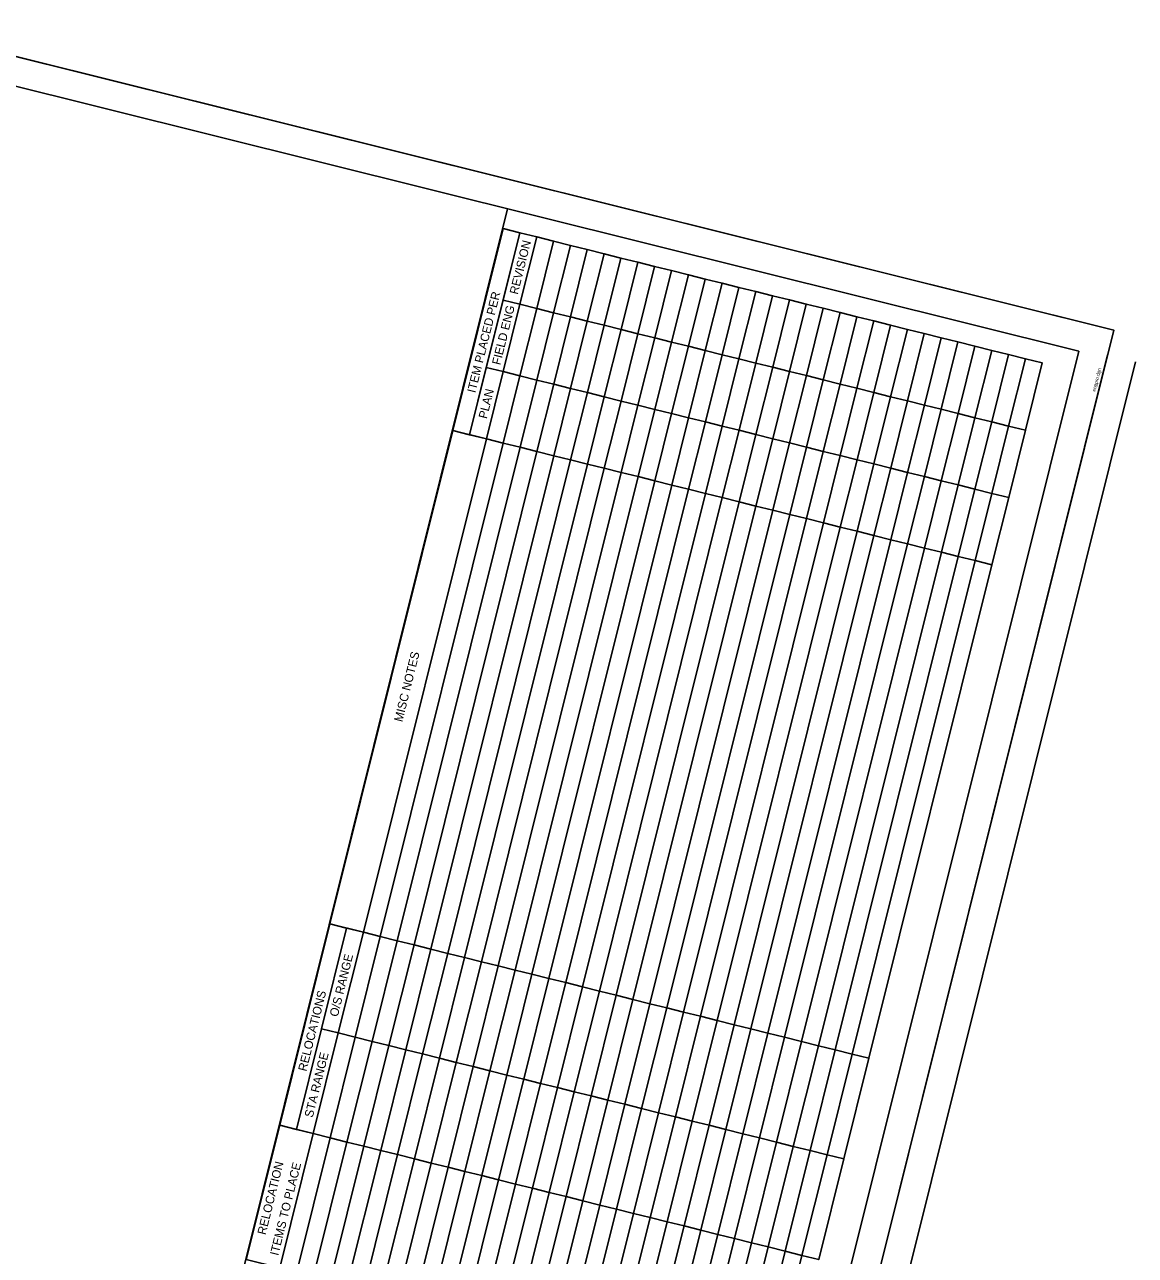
# Model space of a CAD drawing. Extents: x 2304552 to 2306093, y 413849 to 415858.
# Drawn here: x 2305126 to 2306093, y 414787 to 415858 of the extents above; entities that cross this region are included whole.
import ezdxf

# ---------------------------------------------------------------- set-up
doc = ezdxf.new("R2010")
doc.units = 0
for name, color, linetype in [('RD_SHT_Bndy', 7, 'Continuous'), ('RD_SHT_Iplotshp', 7, 'Continuous'), ('RD_SHT_MjGrid', 7, 'Continuous'), ('RD_SHT_Snap', 7, 'Continuous'), ('RD_SHT_TX', 7, 'Continuous')]:
    doc.layers.add(name, color=color, linetype=linetype)

msp = doc.modelspace()

# ---------------------------------------------------------------- linework, layer by layer
at = {"layer": 'RD_SHT_Bndy'}
for p, q in [((2306043.7, 415574), (2305024.9, 415827.9)), ((2305141.5, 414072.6), (2305546.4, 415697.9)), ((2305638.8, 413948.7), (2306043.7, 415574)), ((2306068.6, 415570.6), (2305643.1, 413862.8)), ((2306092.9, 415564.5), (2305667.4, 413856.7))]:
    msp.add_line(p, q, dxfattribs=at)
at = {"layer": 'RD_SHT_Iplotshp'}
msp.add_lwpolyline([(2304572.5, 414115.5), (2305006.6, 415858.2), (2306074, 415592.3), (2305639.9, 413849.6)], close=True, dxfattribs=at)
at = {"layer": 'RD_SHT_MjGrid'}
for points in [[(2305498.7, 415504.8), (2305542.5, 415680.6), (2305557.1, 415676.9), (2305513.4, 415501.2)], [(2305557.2, 415614.7), (2305571.8, 415673.3), (2305557.1, 415676.9), (2305542.5, 415618.3)], [(2305571.8, 415673.3), (2305557.2, 415614.7), (2305571.8, 415611), (2305586.4, 415669.6)], [(2305586.4, 415669.6), (2305571.8, 415611), (2305586.5, 415607.4), (2305601.1, 415666)], [(2305601.1, 415666), (2305586.5, 415607.4), (2305601.2, 415603.7), (2305615.8, 415662.3)], [(2305615.8, 415662.3), (2305601.2, 415603.7), (2305615.8, 415600.1), (2305630.4, 415658.7)], [(2305630.4, 415658.7), (2305615.8, 415600.1), (2305630.5, 415596.4), (2305645.1, 415655)], [(2305645.1, 415655), (2305630.5, 415596.4), (2305645.2, 415592.8), (2305659.8, 415651.4)], [(2305659.8, 415651.4), (2305645.2, 415592.8), (2305659.8, 415589.1), (2305674.4, 415647.7)], [(2305674.4, 415647.7), (2305659.8, 415589.1), (2305674.5, 415585.5), (2305689.1, 415644)], [(2305689.1, 415644), (2305674.5, 415585.5), (2305689.2, 415581.8), (2305703.8, 415640.4)], [(2305703.8, 415640.4), (2305689.2, 415581.8), (2305703.8, 415578.2), (2305718.4, 415636.7)], [(2305718.4, 415636.7), (2305703.8, 415578.2), (2305718.5, 415574.5), (2305733.1, 415633.1)], [(2305733.1, 415633.1), (2305718.5, 415574.5), (2305733.2, 415570.8), (2305747.8, 415629.4)], [(2305747.8, 415629.4), (2305733.2, 415570.8), (2305747.8, 415567.2), (2305762.4, 415625.8)], [(2305542.6, 415556.1), (2305557.2, 415614.7), (2305542.5, 415618.3), (2305527.9, 415559.8)], [(2305762.4, 415625.8), (2305747.8, 415567.2), (2305762.5, 415563.5), (2305777.1, 415622.1)], [(2305777.1, 415622.1), (2305762.5, 415563.5), (2305777.2, 415559.9), (2305791.8, 415618.5)], [(2305791.8, 415618.5), (2305777.2, 415559.9), (2305791.8, 415556.2), (2305806.4, 415614.8)], [(2305557.2, 415614.7), (2305542.6, 415556.1), (2305557.2, 415552.5), (2305571.8, 415611)], [(2305571.8, 415611), (2305557.2, 415552.5), (2305571.9, 415548.8), (2305586.5, 415607.4)], [(2305586.5, 415607.4), (2305571.9, 415548.8), (2305586.6, 415545.2), (2305601.2, 415603.7)], [(2305806.4, 415614.8), (2305791.8, 415556.2), (2305806.5, 415552.6), (2305821.1, 415611.2)], [(2305821.1, 415611.2), (2305806.5, 415552.6), (2305821.2, 415548.9), (2305835.8, 415607.5)], [(2305835.8, 415607.5), (2305821.2, 415548.9), (2305835.8, 415545.3), (2305850.4, 415603.8)], [(2305601.2, 415603.7), (2305586.6, 415545.2), (2305601.2, 415541.5), (2305615.8, 415600.1)], [(2305615.8, 415600.1), (2305601.2, 415541.5), (2305615.9, 415537.8), (2305630.5, 415596.4)], [(2305630.5, 415596.4), (2305615.9, 415537.8), (2305630.6, 415534.2), (2305645.2, 415592.8)], [(2305850.4, 415603.8), (2305835.8, 415545.3), (2305850.5, 415541.6), (2305865.1, 415600.2)], [(2305865.1, 415600.2), (2305850.5, 415541.6), (2305865.2, 415538), (2305879.8, 415596.5)], [(2305879.8, 415596.5), (2305865.2, 415538), (2305879.8, 415534.3), (2305894.4, 415592.9)], [(2305645.2, 415592.8), (2305630.6, 415534.2), (2305645.2, 415530.5), (2305659.8, 415589.1)], [(2305659.8, 415589.1), (2305645.2, 415530.5), (2305659.9, 415526.9), (2305674.5, 415585.5)], [(2305674.5, 415585.5), (2305659.9, 415526.9), (2305674.6, 415523.2), (2305689.2, 415581.8)], [(2305894.4, 415592.9), (2305879.8, 415534.3), (2305894.5, 415530.7), (2305909.1, 415589.2)], [(2305909.1, 415589.2), (2305894.5, 415530.7), (2305909.2, 415527), (2305923.8, 415585.6)], [(2305923.8, 415585.6), (2305909.2, 415527), (2305923.8, 415523.3), (2305938.4, 415581.9)], [(2305689.2, 415581.8), (2305674.6, 415523.2), (2305689.2, 415519.6), (2305703.8, 415578.2)], [(2305703.8, 415578.2), (2305689.2, 415519.6), (2305703.9, 415515.9), (2305718.5, 415574.5)], [(2305718.5, 415574.5), (2305703.9, 415515.9), (2305718.6, 415512.3), (2305733.2, 415570.8)], [(2305938.4, 415581.9), (2305923.8, 415523.3), (2305938.5, 415519.7), (2305953.1, 415578.3)], [(2305953.1, 415578.3), (2305938.5, 415519.7), (2305953.2, 415516), (2305967.8, 415574.6)], [(2305967.8, 415574.6), (2305953.2, 415516), (2305967.8, 415512.4), (2305982.4, 415571)], [(2305733.2, 415570.8), (2305718.6, 415512.3), (2305733.2, 415508.6), (2305747.8, 415567.2)], [(2305747.8, 415567.2), (2305733.2, 415508.6), (2305747.9, 415505), (2305762.5, 415563.5)], [(2305762.5, 415563.5), (2305747.9, 415505), (2305762.6, 415501.3), (2305777.2, 415559.9)], [(2305982.4, 415571), (2305967.8, 415512.4), (2305982.5, 415508.7), (2305997.1, 415567.3)], [(2305997.1, 415567.3), (2305982.5, 415508.7), (2305997.2, 415505.1), (2306011.8, 415563.7)], [(2305528, 415497.5), (2305542.6, 415556.1), (2305527.9, 415559.8), (2305513.4, 415501.2)], [(2305542.6, 415556.1), (2305528, 415497.5), (2305542.6, 415493.9), (2305557.2, 415552.5)], [(2305557.2, 415552.5), (2305542.6, 415493.9), (2305557.3, 415490.2), (2305571.9, 415548.8)], [(2305777.2, 415559.9), (2305762.6, 415501.3), (2305777.2, 415497.7), (2305791.8, 415556.2)], [(2305791.8, 415556.2), (2305777.2, 415497.7), (2305791.9, 415494), (2305806.5, 415552.6)], [(2305806.5, 415552.6), (2305791.9, 415494), (2305806.6, 415490.3), (2305821.2, 415548.9)], [(2305571.9, 415548.8), (2305557.3, 415490.2), (2305572, 415486.6), (2305586.6, 415545.2)], [(2305586.6, 415545.2), (2305572, 415486.6), (2305586.6, 415482.9), (2305601.2, 415541.5)], [(2305601.2, 415541.5), (2305586.6, 415482.9), (2305601.3, 415479.3), (2305615.9, 415537.8)], [(2305821.2, 415548.9), (2305806.6, 415490.3), (2305821.2, 415486.7), (2305835.8, 415545.3)], [(2305835.8, 415545.3), (2305821.2, 415486.7), (2305835.9, 415483), (2305850.5, 415541.6)], [(2305850.5, 415541.6), (2305835.9, 415483), (2305850.6, 415479.4), (2305865.2, 415538)], [(2305615.9, 415537.8), (2305601.3, 415479.3), (2305616, 415475.6), (2305630.6, 415534.2)], [(2305630.6, 415534.2), (2305616, 415475.6), (2305630.6, 415472), (2305645.2, 415530.5)], [(2305645.2, 415530.5), (2305630.6, 415472), (2305645.3, 415468.3), (2305659.9, 415526.9)], [(2305865.2, 415538), (2305850.6, 415479.4), (2305865.2, 415475.7), (2305879.8, 415534.3)], [(2305879.8, 415534.3), (2305865.2, 415475.7), (2305879.9, 415472.1), (2305894.5, 415530.7)], [(2305894.5, 415530.7), (2305879.9, 415472.1), (2305894.6, 415468.4), (2305909.2, 415527)], [(2305659.9, 415526.9), (2305645.3, 415468.3), (2305660, 415464.7), (2305674.6, 415523.2)], [(2305674.6, 415523.2), (2305660, 415464.7), (2305674.6, 415461), (2305689.2, 415519.6)], [(2305689.2, 415519.6), (2305674.6, 415461), (2305689.3, 415457.3), (2305703.9, 415515.9)], [(2305909.2, 415527), (2305894.6, 415468.4), (2305909.2, 415464.8), (2305923.8, 415523.3)], [(2305923.8, 415523.3), (2305909.2, 415464.8), (2305923.9, 415461.1), (2305938.5, 415519.7)], [(2305938.5, 415519.7), (2305923.9, 415461.1), (2305938.6, 415457.5), (2305953.2, 415516)], [(2305703.9, 415515.9), (2305689.3, 415457.3), (2305704, 415453.7), (2305718.6, 415512.3)], [(2305718.6, 415512.3), (2305704, 415453.7), (2305718.6, 415450), (2305733.2, 415508.6)], [(2305733.2, 415508.6), (2305718.6, 415450), (2305733.3, 415446.4), (2305747.9, 415505)], [(2305953.2, 415516), (2305938.6, 415457.5), (2305953.2, 415453.8), (2305967.8, 415512.4)], [(2305967.8, 415512.4), (2305953.2, 415453.8), (2305967.9, 415450.1), (2305982.5, 415508.7)], [(2305982.5, 415508.7), (2305967.9, 415450.1), (2305982.6, 415446.5), (2305997.2, 415505.1)], [(2305391.7, 415075.3), (2305498.7, 415504.8), (2305528, 415497.5), (2305421, 415068)], [(2305747.9, 415505), (2305733.3, 415446.4), (2305748, 415442.7), (2305762.6, 415501.3)], [(2305762.6, 415501.3), (2305748, 415442.7), (2305762.6, 415439.1), (2305777.2, 415497.7)], [(2305777.2, 415497.7), (2305762.6, 415439.1), (2305777.3, 415435.4), (2305791.9, 415494)], [(2305528, 415497.5), (2305421, 415068), (2305435.6, 415064.3), (2305542.6, 415493.9)], [(2305542.6, 415493.9), (2305435.6, 415064.3), (2305450.3, 415060.7), (2305557.3, 415490.2)], [(2305557.3, 415490.2), (2305450.3, 415060.7), (2305465, 415057), (2305572, 415486.6)], [(2305791.9, 415494), (2305777.3, 415435.4), (2305792, 415431.8), (2305806.6, 415490.3)], [(2305806.6, 415490.3), (2305792, 415431.8), (2305806.6, 415428.1), (2305821.2, 415486.7)], [(2305572, 415486.6), (2305465, 415057), (2305479.6, 415053.4), (2305586.6, 415482.9)], [(2305586.6, 415482.9), (2305479.6, 415053.4), (2305494.3, 415049.7), (2305601.3, 415479.3)], [(2305601.3, 415479.3), (2305494.3, 415049.7), (2305509, 415046.1), (2305616, 415475.6)], [(2305821.2, 415486.7), (2305806.6, 415428.1), (2305821.3, 415424.5), (2305835.9, 415483)], [(2305835.9, 415483), (2305821.3, 415424.5), (2305836, 415420.8), (2305850.6, 415479.4)], [(2305850.6, 415479.4), (2305836, 415420.8), (2305850.6, 415417.1), (2305865.2, 415475.7)], [(2305616, 415475.6), (2305509, 415046.1), (2305523.6, 415042.4), (2305630.6, 415472)], [(2305630.6, 415472), (2305523.6, 415042.4), (2305538.3, 415038.8), (2305645.3, 415468.3)], [(2305645.3, 415468.3), (2305538.3, 415038.8), (2305553, 415035.1), (2305660, 415464.7)], [(2305865.2, 415475.7), (2305850.6, 415417.1), (2305865.3, 415413.5), (2305879.9, 415472.1)], [(2305879.9, 415472.1), (2305865.3, 415413.5), (2305880, 415409.8), (2305894.6, 415468.4)], [(2305894.6, 415468.4), (2305880, 415409.8), (2305894.6, 415406.2), (2305909.2, 415464.8)], [(2305660, 415464.7), (2305553, 415035.1), (2305567.6, 415031.5), (2305674.6, 415461)], [(2305674.6, 415461), (2305567.6, 415031.5), (2305582.3, 415027.8), (2305689.3, 415457.3)], [(2305689.3, 415457.3), (2305582.3, 415027.8), (2305597, 415024.2), (2305704, 415453.7)], [(2305909.2, 415464.8), (2305894.6, 415406.2), (2305909.3, 415402.5), (2305923.9, 415461.1)], [(2305923.9, 415461.1), (2305909.3, 415402.5), (2305924, 415398.9), (2305938.6, 415457.5)], [(2305938.6, 415457.5), (2305924, 415398.9), (2305938.6, 415395.2), (2305953.2, 415453.8)], [(2305704, 415453.7), (2305597, 415024.2), (2305611.6, 415020.5), (2305718.6, 415450)], [(2305718.6, 415450), (2305611.6, 415020.5), (2305626.3, 415016.8), (2305733.3, 415446.4)], [(2305733.3, 415446.4), (2305626.3, 415016.8), (2305641, 415013.2), (2305748, 415442.7)], [(2305953.2, 415453.8), (2305938.6, 415395.2), (2305953.3, 415391.6), (2305967.9, 415450.1)], [(2305967.9, 415450.1), (2305953.3, 415391.6), (2305968, 415387.9), (2305982.6, 415446.5)], [(2305748, 415442.7), (2305641, 415013.2), (2305655.6, 415009.5), (2305762.6, 415439.1)], [(2305762.6, 415439.1), (2305655.6, 415009.5), (2305670.3, 415005.9), (2305777.3, 415435.4)], [(2305777.3, 415435.4), (2305670.3, 415005.9), (2305685, 415002.2), (2305792, 415431.8)], [(2305792, 415431.8), (2305685, 415002.2), (2305699.6, 414998.6), (2305806.6, 415428.1)], [(2305806.6, 415428.1), (2305699.6, 414998.6), (2305714.3, 414994.9), (2305821.3, 415424.5)], [(2305821.3, 415424.5), (2305714.3, 414994.9), (2305729, 414991.3), (2305836, 415420.8)], [(2305836, 415420.8), (2305729, 414991.3), (2305743.6, 414987.6), (2305850.6, 415417.1)], [(2305850.6, 415417.1), (2305743.6, 414987.6), (2305758.3, 414984), (2305865.3, 415413.5)], [(2305865.3, 415413.5), (2305758.3, 414984), (2305773, 414980.3), (2305880, 415409.8)], [(2305880, 415409.8), (2305773, 414980.3), (2305787.6, 414976.6), (2305894.6, 415406.2)], [(2305894.6, 415406.2), (2305787.6, 414976.6), (2305802.3, 414973), (2305909.3, 415402.5)], [(2305909.3, 415402.5), (2305802.3, 414973), (2305817, 414969.3), (2305924, 415398.9)], [(2305924, 415398.9), (2305817, 414969.3), (2305831.6, 414965.7), (2305938.6, 415395.2)], [(2305938.6, 415395.2), (2305831.6, 414965.7), (2305846.3, 414962), (2305953.3, 415391.6)], [(2305953.3, 415391.6), (2305846.3, 414962), (2305861, 414958.4), (2305968, 415387.9)], [(2305348.1, 414900), (2305391.7, 415075.3), (2305406.3, 415071.6), (2305362.7, 414896.4)], [(2305399.1, 414980.4), (2305421, 415068), (2305406.3, 415071.6), (2305384.5, 414984)], [(2305421, 415068), (2305399.1, 414980.4), (2305413.8, 414976.7), (2305435.6, 415064.3)], [(2305435.6, 415064.3), (2305413.8, 414976.7), (2305428.5, 414973.1), (2305450.3, 415060.7)], [(2305450.3, 415060.7), (2305428.5, 414973.1), (2305443.1, 414969.4), (2305465, 415057)], [(2305465, 415057), (2305443.1, 414969.4), (2305457.8, 414965.8), (2305479.6, 415053.4)], [(2305479.6, 415053.4), (2305457.8, 414965.8), (2305472.5, 414962.1), (2305494.3, 415049.7)], [(2305494.3, 415049.7), (2305472.5, 414962.1), (2305487.1, 414958.5), (2305509, 415046.1)], [(2305509, 415046.1), (2305487.1, 414958.5), (2305501.8, 414954.8), (2305523.6, 415042.4)], [(2305523.6, 415042.4), (2305501.8, 414954.8), (2305516.5, 414951.1), (2305538.3, 415038.8)], [(2305538.3, 415038.8), (2305516.5, 414951.1), (2305531.1, 414947.5), (2305553, 415035.1)], [(2305553, 415035.1), (2305531.1, 414947.5), (2305545.8, 414943.8), (2305567.6, 415031.5)], [(2305567.6, 415031.5), (2305545.8, 414943.8), (2305560.5, 414940.2), (2305582.3, 415027.8)], [(2305582.3, 415027.8), (2305560.5, 414940.2), (2305575.1, 414936.5), (2305597, 415024.2)], [(2305597, 415024.2), (2305575.1, 414936.5), (2305589.8, 414932.9), (2305611.6, 415020.5)], [(2305611.6, 415020.5), (2305589.8, 414932.9), (2305604.5, 414929.2), (2305626.3, 415016.8)], [(2305626.3, 415016.8), (2305604.5, 414929.2), (2305619.1, 414925.6), (2305641, 415013.2)], [(2305641, 415013.2), (2305619.1, 414925.6), (2305633.8, 414921.9), (2305655.6, 415009.5)], [(2305655.6, 415009.5), (2305633.8, 414921.9), (2305648.5, 414918.3), (2305670.3, 415005.9)], [(2305670.3, 415005.9), (2305648.5, 414918.3), (2305663.1, 414914.6), (2305685, 415002.2)], [(2305685, 415002.2), (2305663.1, 414914.6), (2305677.8, 414910.9), (2305699.6, 414998.6)], [(2305699.6, 414998.6), (2305677.8, 414910.9), (2305692.5, 414907.3), (2305714.3, 414994.9)], [(2305714.3, 414994.9), (2305692.5, 414907.3), (2305707.1, 414903.6), (2305729, 414991.3)], [(2305377.3, 414892.8), (2305399.1, 414980.4), (2305384.5, 414984), (2305362.7, 414896.4)], [(2305729, 414991.3), (2305707.1, 414903.6), (2305721.8, 414900), (2305743.6, 414987.6)], [(2305743.6, 414987.6), (2305721.8, 414900), (2305736.5, 414896.3), (2305758.3, 414984)], [(2305758.3, 414984), (2305736.5, 414896.3), (2305751.1, 414892.7), (2305773, 414980.3)], [(2305399.1, 414980.4), (2305377.3, 414892.8), (2305392, 414889.1), (2305413.8, 414976.7)], [(2305413.8, 414976.7), (2305392, 414889.1), (2305406.6, 414885.4), (2305428.5, 414973.1)], [(2305428.5, 414973.1), (2305406.6, 414885.4), (2305421.3, 414881.8), (2305443.1, 414969.4)], [(2305773, 414980.3), (2305751.1, 414892.7), (2305765.8, 414889), (2305787.6, 414976.6)], [(2305787.6, 414976.6), (2305765.8, 414889), (2305780.5, 414885.4), (2305802.3, 414973)], [(2305802.3, 414973), (2305780.5, 414885.4), (2305795.1, 414881.7), (2305817, 414969.3)], [(2305443.1, 414969.4), (2305421.3, 414881.8), (2305436, 414878.1), (2305457.8, 414965.8)], [(2305457.8, 414965.8), (2305436, 414878.1), (2305450.6, 414874.5), (2305472.5, 414962.1)], [(2305472.5, 414962.1), (2305450.6, 414874.5), (2305465.3, 414870.8), (2305487.1, 414958.5)], [(2305817, 414969.3), (2305795.1, 414881.7), (2305809.8, 414878.1), (2305831.6, 414965.7)], [(2305831.6, 414965.7), (2305809.8, 414878.1), (2305824.5, 414874.4), (2305846.3, 414962)], [(2305846.3, 414962), (2305824.5, 414874.4), (2305839.1, 414870.8), (2305861, 414958.4)], [(2305487.1, 414958.5), (2305465.3, 414870.8), (2305480, 414867.2), (2305501.8, 414954.8)], [(2305501.8, 414954.8), (2305480, 414867.2), (2305494.6, 414863.5), (2305516.5, 414951.1)], [(2305516.5, 414951.1), (2305494.6, 414863.5), (2305509.3, 414859.9), (2305531.1, 414947.5)], [(2305531.1, 414947.5), (2305509.3, 414859.9), (2305524, 414856.2), (2305545.8, 414943.8)], [(2305545.8, 414943.8), (2305524, 414856.2), (2305538.6, 414852.6), (2305560.5, 414940.2)], [(2305560.5, 414940.2), (2305538.6, 414852.6), (2305553.3, 414848.9), (2305575.1, 414936.5)], [(2305575.1, 414936.5), (2305553.3, 414848.9), (2305568, 414845.2), (2305589.8, 414932.9)], [(2305589.8, 414932.9), (2305568, 414845.2), (2305582.6, 414841.6), (2305604.5, 414929.2)], [(2305604.5, 414929.2), (2305582.6, 414841.6), (2305597.3, 414837.9), (2305619.1, 414925.6)], [(2305619.1, 414925.6), (2305597.3, 414837.9), (2305612, 414834.3), (2305633.8, 414921.9)], [(2305633.8, 414921.9), (2305612, 414834.3), (2305626.6, 414830.6), (2305648.5, 414918.3)], [(2305648.5, 414918.3), (2305626.6, 414830.6), (2305641.3, 414827), (2305663.1, 414914.6)], [(2305663.1, 414914.6), (2305641.3, 414827), (2305656, 414823.3), (2305677.8, 414910.9)], [(2305677.8, 414910.9), (2305656, 414823.3), (2305670.6, 414819.7), (2305692.5, 414907.3)], [(2305319, 414783.3), (2305348.1, 414900), (2305377.3, 414892.8), (2305348.2, 414776)], [(2305692.5, 414907.3), (2305670.6, 414819.7), (2305685.3, 414816), (2305707.1, 414903.6)], [(2305707.1, 414903.6), (2305685.3, 414816), (2305700, 414812.4), (2305721.8, 414900)], [(2305721.8, 414900), (2305700, 414812.4), (2305714.6, 414808.7), (2305736.5, 414896.3)], [(2305377.3, 414892.8), (2305348.2, 414776), (2305362.9, 414772.4), (2305392, 414889.1)], [(2305392, 414889.1), (2305362.9, 414772.4), (2305377.6, 414768.7), (2305406.6, 414885.4)], [(2305736.5, 414896.3), (2305714.6, 414808.7), (2305729.3, 414805.1), (2305751.1, 414892.7)], [(2305751.1, 414892.7), (2305729.3, 414805.1), (2305744, 414801.4), (2305765.8, 414889)], [(2305765.8, 414889), (2305744, 414801.4), (2305758.6, 414797.7), (2305780.5, 414885.4)], [(2305406.6, 414885.4), (2305377.6, 414768.7), (2305392.2, 414765.1), (2305421.3, 414881.8)], [(2305421.3, 414881.8), (2305392.2, 414765.1), (2305406.9, 414761.4), (2305436, 414878.1)], [(2305436, 414878.1), (2305406.9, 414761.4), (2305421.6, 414757.8), (2305450.6, 414874.5)], [(2305780.5, 414885.4), (2305758.6, 414797.7), (2305773.3, 414794.1), (2305795.1, 414881.7)], [(2305795.1, 414881.7), (2305773.3, 414794.1), (2305788, 414790.4), (2305809.8, 414878.1)], [(2305809.8, 414878.1), (2305788, 414790.4), (2305802.6, 414786.8), (2305824.5, 414874.4)], [(2305450.6, 414874.5), (2305421.6, 414757.8), (2305436.2, 414754.1), (2305465.3, 414870.8)], [(2305465.3, 414870.8), (2305436.2, 414754.1), (2305450.9, 414750.5), (2305480, 414867.2)], [(2305480, 414867.2), (2305450.9, 414750.5), (2305465.6, 414746.8), (2305494.6, 414863.5)], [(2305824.5, 414874.4), (2305802.6, 414786.8), (2305817.3, 414783.1), (2305839.1, 414870.8)], [(2305494.6, 414863.5), (2305465.6, 414746.8), (2305480.2, 414743.2), (2305509.3, 414859.9)], [(2305509.3, 414859.9), (2305480.2, 414743.2), (2305494.9, 414739.5), (2305524, 414856.2)], [(2305524, 414856.2), (2305494.9, 414739.5), (2305509.6, 414735.8), (2305538.6, 414852.6)], [(2305538.6, 414852.6), (2305509.6, 414735.8), (2305524.2, 414732.2), (2305553.3, 414848.9)], [(2305553.3, 414848.9), (2305524.2, 414732.2), (2305538.9, 414728.5), (2305568, 414845.2)], [(2305568, 414845.2), (2305538.9, 414728.5), (2305553.6, 414724.9), (2305582.6, 414841.6)], [(2305582.6, 414841.6), (2305553.6, 414724.9), (2305568.2, 414721.2), (2305597.3, 414837.9)], [(2305597.3, 414837.9), (2305568.2, 414721.2), (2305582.9, 414717.6), (2305612, 414834.3)], [(2305612, 414834.3), (2305582.9, 414717.6), (2305597.6, 414713.9), (2305626.6, 414830.6)], [(2305626.6, 414830.6), (2305597.6, 414713.9), (2305612.2, 414710.3), (2305641.3, 414827)], [(2305641.3, 414827), (2305612.2, 414710.3), (2305626.9, 414706.6), (2305656, 414823.3)], [(2305656, 414823.3), (2305626.9, 414706.6), (2305641.6, 414703), (2305670.6, 414819.7)], [(2305670.6, 414819.7), (2305641.6, 414703), (2305656.2, 414699.3), (2305685.3, 414816)], [(2305685.3, 414816), (2305656.2, 414699.3), (2305670.9, 414695.7), (2305700, 414812.4)], [(2305700, 414812.4), (2305670.9, 414695.7), (2305685.6, 414692), (2305714.6, 414808.7)], [(2305714.6, 414808.7), (2305685.6, 414692), (2305700.2, 414688.3), (2305729.3, 414805.1)], [(2305729.3, 414805.1), (2305700.2, 414688.3), (2305714.9, 414684.7), (2305744, 414801.4)], [(2305744, 414801.4), (2305714.9, 414684.7), (2305729.6, 414681), (2305758.6, 414797.7)], [(2305758.6, 414797.7), (2305729.6, 414681), (2305744.2, 414677.4), (2305773.3, 414794.1)], [(2305773.3, 414794.1), (2305744.2, 414677.4), (2305758.9, 414673.7), (2305788, 414790.4)], [(2305788, 414790.4), (2305758.9, 414673.7), (2305773.6, 414670.1), (2305802.6, 414786.8)]]:
    msp.add_lwpolyline(points, close=True, dxfattribs=at)
at = {"layer": 'RD_SHT_Snap'}
msp.add_line((2306074, 415592.3), (2305006.6, 415858.2), dxfattribs=at)

# ---------------------------------------------------------------- texts
at = {"layer": 'RD_SHT_TX'}
for s, height, p in [('REVISION', 7.5, (2305555.3, 415622.8)), ('ITEM PLACED PER', 7.5, (2305518.4, 415537.1)), ('FIELD ENG', 7.5, (2305540, 415561.4)), ('engpro.dgn', 3, (2306058.1, 415538.5)), ('PLAN', 7.5, (2305528.3, 415514.6)), ('MISC NOTES', 7.5, (2305454.8, 415250.7)), ('O/S RANGE', 7.5, (2305398.6, 414994)), ('RELOCATIONS', 7.5, (2305371.3, 414946.5)), ('STA RANGE', 7.5, (2305376.8, 414906.3)), ('RELOCATION', 7.5, (2305335.8, 414804.2)), ('ITEMS TO PLACE', 7.5, (2305346.8, 414786.1))]:
    msp.add_text(s, height=height, rotation=76.0103, dxfattribs=at).set_placement(p)

doc.saveas('drawing.dxf')
